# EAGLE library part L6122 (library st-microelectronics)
100 V DMOS SWITCHES
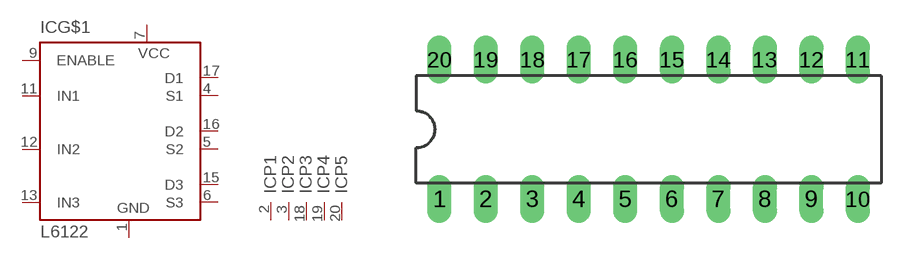
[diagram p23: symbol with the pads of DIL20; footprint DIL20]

Designator prefix IC; gates G$1=L6122 P1=GND P2=GND P3=GND P4=GND P5=GND

## L6122 (OC_FARNELL: unknown; OC_NEWARK: unknown)  [DIL20]
1  G$1:GND  pwr
2  P1:GND  pwr
3  P2:GND  pwr
4  G$1:S1  pas
5  G$1:S2  pas
6  G$1:S3  pas
7  G$1:VCC  pwr
9  G$1:ENABLE  in
11  G$1:IN1  in
12  G$1:IN2  in
13  G$1:IN3  in
15  G$1:D3  pas
16  G$1:D2  pas
17  G$1:D1  pas
18  P3:GND  pwr
19  P4:GND  pwr
20  P5:GND  pwr

## Footprint DIL20 (pad centres in mm)
Dual In Line Package
drill 0.813 long: 1 -11.43,-3.81; 2 -8.89,-3.81; 3 -6.35,-3.81; 4 -3.81,-3.81; 5 -1.27,-3.81; 6 1.27,-3.81; 7 3.81,-3.81; 8 6.35,-3.81; 9 8.89,-3.81; 10 11.43,-3.81; 11 11.43,3.81; 12 8.89,3.81; 13 6.35,3.81; 14 3.81,3.81; 15 1.27,3.81; 16 -1.27,3.81; 17 -3.81,3.81; 18 -6.35,3.81; 19 -8.89,3.81; 20 -11.43,3.81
